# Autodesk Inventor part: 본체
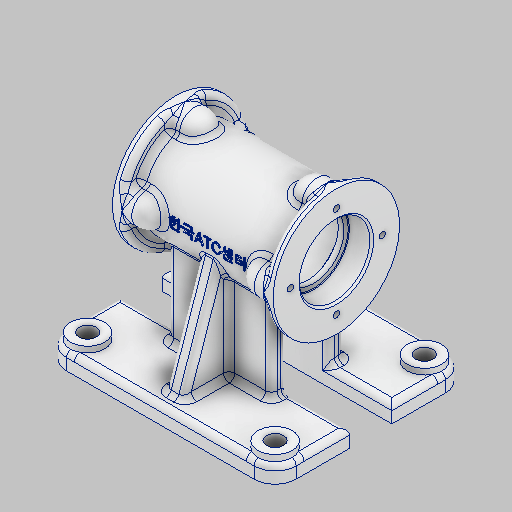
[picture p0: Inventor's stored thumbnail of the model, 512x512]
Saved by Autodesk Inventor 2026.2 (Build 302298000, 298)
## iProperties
Created: 2026-06
Part Number: 본체
Material: 알루미늄 6061
Document SubType Name: Modeling
Designer: sec7
Density: 2.7 g/cm^3
Appearance: 알루미늄 - 평지
Mass: 617.574 g
Surface Area: 687.665 cm^2
Volume: 228.731 cm^3
Author: sec7
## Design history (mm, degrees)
sketch "스케치1"
  geometry: L1 (-42, 0)-(42, 0); L2 (-42, 16)-(42, 16); L3 (42, 16)-(42, 0); L4 (-42, 18.5)-(-30.3, 18.5); L5 (-42, 18.5)-(-42, 0); L6 (-30, 18.2)-(-30, 0); L7 (-27, 0)-(-27, 17); L8 (-24, 20)-(24, 20); L9 (27, 17)-(27, 0); L10 (30, 0)-(30, 18.2); L11 (30.3, 18.5)-(42, 18.5); L12 (42, 18.5)-(42, 16); L13 (-42, 18.5)-(-42, 33); L14 (-42, 33)-(-37, 33); L15 (-37, 33)-(-37, 25); L16 (-37, 25)-(37, 25); L17 (37, 25)-(37, 33); L18 (37, 33)-(42, 33); L19 (42, 33)-(42, 18.5); L20 (-37, 29.455)-(-32, 29.455); L21 (-37, 25)-(-24.828, 25); A1 r 0.3 centre (-30.3, 18.2) between (-30, 18.2) and (-30.3, 18.5); A2 r 0.3 centre (30.3, 18.2) between (30.3, 18.5) and (30, 18.2); A3 r 3 centre (-24, 17) between (-24, 20) and (-27, 17); A4 r 3 centre (24, 17) between (27, 17) and (24, 20); A5 r 8 centre (-32, 21.455) between (-24.828, 25) and (-32, 29.455); 13 further points
  constraints: 42 end point, 14 point on line, 12 perpendicular, 10 point on circle, 9 tangent, 5 centre point, 4 vertical, 3 horizontal, 2 coincident, 2 equal radius, 2 midpoint, 1 collinear, 1 vertical alignment
  dimensions: "d1" = 84 distance of L1.start L1.end; "d3" = 32 diameter of L2 L1; "d4" = 37 diameter of L4 L1; "d5" = 40 diameter of L8 L1; "d6" = 54 distance between parallel lines of L9 L7; "d7" = 12 distance between parallel lines of L6 L5; "d8" = 37 diameter of L11 L1; "d9" = 12 distance between parallel lines of L3 L10; "d11" = 66 diameter of L14 L1; "d12" = 66 diameter of L18 L1; "d13" = 50 diameter of L16 L1; "d14" = 5 distance between parallel lines of L15 L13; "d15" = 5 distance between parallel lines of L19 L17; "d17" = 0.3 radius of A1; "d118" = 3 radius of A3; "d119" = 10 distance from line of L20.end L13; "d120" = 8 radius of A5; "d144" = 17.17158 distance from line of L21.end L13
revolve "회전1" sketch "스케치1" stored, may be unused: angle "d16" = 360 deg
node "작업 평면2"
sketch "스케치3"
  geometry: L1 (-60, 50)-(60, 50); L2 (60, 50)-(60, -50); L3 (60, -50)-(-60, -50); L4 (-60, -50)-(-60, 50); L5 (-60, 50)-(60, -50); L6 (60, 50)-(-60, -50); L7 (60, -11)-(-60, -11); L8 (60, 11)-(-60, 11); 1 further point
  constraints: 16 end point, 4 point on line, 3 perpendicular, 2 midpoint, 2 parallel, 1 horizontal
  dimensions: "d26" = 120 distance of L2.end L3.end; "d27" = 100 distance of L1.end L2.end; "d28" = 39 distance between parallel lines of L7 L3; "d29" = 39 distance between parallel lines of L1 L8
extrude "돌출2" join sketch "스케치3" distance "d30" = 9; taper "d31" = 0 deg
sketch "스케치4"
  geometry: L1 (49, -39)-(-49, -39); L2 (-49, -39)-(-49, 39); L3 (-49, 39)-(49, 39); L4 (49, 39)-(49, -39); L5 (49, -39)-(-49, 39); L6 (-49, -39)-(49, 39); C1 r 9 at (-49, 39); C2 r 9 at (49, 39); C3 r 9 at (49, -39); C4 r 9 at (-49, -39); 1 further point
  constraints: 12 end point, 4 centre point, 4 coincident, 2 midpoint, 2 parallel, 1 horizontal, 1 perpendicular
  dimensions: "d32" = 98 distance of L2.end L3.end; "d33" = 78 distance of L1.end L2.end; "d34" = 18 diameter of C1; "d35" = 18 diameter of C2; "d36" = 18 diameter of C3; "d37" = 18 diameter of C4
extrude "돌출3" join sketch "스케치4" distance "d38" = 3; taper "d39" = 0 deg
sketch "스케치5"
  geometry: L1 (0, 0)-(98, 0); L2 (98, 0)-(98, 78); L3 (98, 78)-(0, 78); L4 (0, 78)-(0, 0); C1 r 9 at (0, 0) reference; C2 r 9 at (98, 78) reference; C3 r 4.5 at (0, 0); C4 r 4.5 at (0, 78); C5 r 4.5 at (98, 78); C6 r 4.5 at (98, 0); 1 further point
  constraints: 8 end point, 4 centre point, 4 coincident, 2 parallel, 1 horizontal, 1 perpendicular
  dimensions: "d40" = 9 diameter of C3; "d41" = 9 diameter of C4; "d42" = 9 diameter of C5; "d43" = 9 diameter of C6
extrude "돌출4" cut sketch "스케치5" extent not by distance; stored distance "d44" = 0; taper "d45" = 0 deg
sketch "스케치6"
  geometry: L1 (-60, 11)-(60, 11) reference; L2 (60, -11)-(-60, -11) reference; L3 (-27, -11)-(27, -11); L4 (-27, 11)-(27, 11); L5 (-27, -11)-(-27, -19); L6 (-27, -19)-(27, -19); L7 (27, -19)-(27, -11); L8 (-27, 11)-(-27, 19); L9 (-27, 19)-(27, 19); L10 (27, 19)-(27, 11); 7 further points
  constraints: 16 end point, 4 midpoint, 4 perpendicular, 2 horizontal, 2 vertical
  dimensions: "d46" = 54 distance of L3.start L3.end; "d47" = 54 distance of L4.start L4.end; "d48" = 8 distance of L3.start L5.end; "d49" = 8 distance of L4.start L8.end
extrude "돌출5" join sketch "스케치6" stored distance "d50" = 10; taper "d51" = 0 deg
sketch "스케치7"
  geometry: L1 (-61, 50)-(-61, 11) reference; L2 (-17.454, 28.006)-(-61, 43); L3 (-70, 50)-(-61, 50) reference; L4 (-61, 19)-(-16.248, 19) reference; 2 further points
  constraints: 2 end point, 1 point on line, 2 other
  dimensions: "d52" = 7 distance from line of L2.end L3; "d53" = 19 deg angle of L4 L2
feature "리브1" sketch "스케치7" dims "d54" = 1, "d55" = 10, "d56" = 0, "d57" = 0, "d58" = 1, "d59" = 1
node "작업 평면1"
sketch "스케치2"
  geometry: L1 (25, 0)-(-25, 0); L2 (0, 25)-(0, -25); C1 r 8 at (25, 0); C2 r 8 at (0, 25); C3 r 8 at (-25, 0); C4 r 8 at (0, -25); A1 r 25 centre (0, 0) between (25, 0) and (0, 25) reference; 9 further points
  constraints: 4 centre point, 4 end point, 4 point on circle, 1 horizontal, 1 vertical
  dimensions: "d19" = 16 diameter of C1; "d20" = 16 diameter of C2; "d21" = 16 diameter of C3; "d22" = 16 diameter of C4; "d73" = 50 distance of L1.start L1.end; "d74" = 50 distance of L2.start L2.end
extrude "돌출1" join sketch "스케치2" distance "d23" = 5; taper "d24" = 0 deg
sketch "스케치10"
  geometry: L1 (-3.55, 23.157)-(3.55, 23.157); A1 r 25 centre (0, 0) between (23.72, 7.897) and (7.897, 23.72) reference; A2 r 25 centre (0, 0) between (-7.897, 23.72) and (-23.72, 7.897) reference; A3 r 8 centre (0, 25) between (7.897, 23.72) and (-7.897, 23.72) reference; A4 r 25 centre (0, 0) between (7.897, 23.72) and (-7.897, 23.72); A5 r 4 centre (0, 25) between (-3.55, 23.157) and (3.55, 23.157); 1 further point
  constraints: 4 point on circle, 2 centre point, 2 coincident, 2 end point, 1 horizontal
revolve "회전3" sketch "스케치10" stored, may be unused: angle "d71" = 180 deg
fillet "모깎기1" dims "d72" = 3
fillet "모깎기2" dims "d95" = 3
sketch "스케치13"
  geometry: L1 (-42, 0)-(42, 0); L2 (-42, 16)-(42, 16); L3 (42, 16)-(42, 0); L4 (-42, 18.5)-(-30.3, 18.5); L5 (-42, 18.5)-(-42, 0); L6 (-30, 18.2)-(-30, 0); L7 (-27, 0)-(-27, 17); L8 (-24, 20)-(24, 20); L9 (27, 17)-(27, 0); L10 (30, 0)-(30, 18.2); L11 (30.3, 18.5)-(42, 18.5); L12 (42, 18.5)-(42, 16); L13 (-42, 18.5)-(-42, 33); L14 (-42, 33)-(-37, 33); L15 (-37, 33)-(-37, 25); L16 (-37, 25)-(37, 25); L17 (37, 25)-(37, 33); L18 (37, 33)-(42, 33); L19 (42, 33)-(42, 18.5); A1 r 0.3 centre (-30.3, 18.2) between (-30, 18.2) and (-30.3, 18.5); A2 r 0.3 centre (30.3, 18.2) between (30.3, 18.5) and (30, 18.2); A3 r 3 centre (-24, 17) between (-24, 20) and (-27, 17); A4 r 3 centre (24, 17) between (27, 17) and (24, 20); 21 further points
  constraints: 38 end point, 12 perpendicular, 8 point on circle, 8 point on line, 8 tangent, 4 centre point, 4 coincident, 4 vertical, 2 equal radius, 2 horizontal, 2 midpoint, 1 vertical alignment
  dimensions: "d156" = 84 distance of L1.start L1.end; "d157" = 32 diameter of L2 L1; "d158" = 37 diameter of L4 L1; "d159" = 40 diameter of L8 L1; "d160" = 54 distance between parallel lines of L9 L7; "d161" = 12 distance between parallel lines of L6 L5; "d162" = 37 diameter of L11 L1; "d163" = 12 distance between parallel lines of L3 L10; "d164" = 84 distance from line of L2.start L12; "d165" = 66 diameter of L14 L1; "d166" = 66 diameter of L18 L1; "d167" = 50 diameter of L16 L1; "d168" = 5 distance between parallel lines of L15 L13; "d169" = 5 distance between parallel lines of L19 L17; "d170" = 0.3 radius of A1; "d173" = 3 radius of A3
revolve "회전4" sketch "스케치13" stored, may be unused: angle "d174" = 360 deg
sketch "스케치14"
  geometry: L1 (-70, 50)-(-70, 11) reference; L2 (-70, -11)-(-70, -50) reference; L3 (-70, 11)-(-70, -11); L4 (-70, 0)-(-50, 0); L5 (-61, 11)-(-22.45, 11) reference; L6 (-50, 11)-(-50, -11); L7 (-61, -11)-(-22.45, -11) reference; L8 (-61, 11)-(-22.45, 11) reference; C1 r 33 at (0, 0) reference; 1 further point
  constraints: 6 end point, 2 vertical, 1 horizontal, 1 midpoint, 1 point on line
  dimensions: "d175" = 20 distance of L4.start L4.end
feature "리브2" sketch "스케치14" dims "d176" = 1, "d177" = 10, "d178" = 0, "d179" = 0, "d180" = 1, "d181" = 1
node "작업 평면3"
sketch "스케치15"
  geometry: L1 (-60, -70)-(60, -70) reference; L2 (0, -70)-(0, 0); 1 further point
  constraints: 2 end point, 1 coincident, 1 midpoint, 1 vertical, 1 other
  dimensions: "d183" = 70 distance of L2.start L2.end (derived)
feature "엠보싱1" sketch "스케치15" dims "d1" = 84, "d3" = 32, "d4" = 37, "d5" = 40, "d6" = 54, "d7" = 12, "d8" = 37, "d9" = 12, "d11" = 66, "d12" = 66, "d13" = 50, "d14" = 5, "d15" = 5, "d17" = 0.3, "d118" = 3, "d119" = 10, "d120" = 8, "d144" = 17.17158, "d184" = 0.5, "d185" = 0
sketch "스케치16"
  geometry: L1 (0, 24)-(0, -24); L2 (-24, 0)-(24, 0); A1 r 24 centre (0, 0) between (0, 24) and (0, -24); 5 further points
  constraints: 5 point on circle, 4 coincident, 4 end point, 1 centre point, 1 perpendicular, 1 vertical
  dimensions: "d186" = 48 diameter of A1; "d187" = 48 distance of L2.start L2.end; "d188" = 48 distance of L1.start L1.end; "d189" = 24 distance from line of point (0, 24) L2
hole "구멍2" sketch "스케치16" at (0, 24), (-24, 0), (24, 0), (0, -24) diameter "d190" = 3.242; stored, may be unused: countersink angle "d194" = 90 deg, drill point angle "d196" = 120 deg; dims "d191" = 8, "d192" = 4, "d193" = 2, "d195" = 10
chamfer "모따기1" distance "d197" = 1; stored, may be unused: second distance "d198" = 2, angle "d199" = 45 deg
chamfer "모따기2" distance "d200" = 1; stored, may be unused: second distance "d201" = 2, angle "d202" = 45 deg
fillet "모깎기4" dims "d204" = 3
fillet "모깎기5" dims "d205" = 11
fillet "모깎기6" dims "d206" = 3
fillet "모깎기7" dims "d207" = 3
fillet "모깎기8" dims "d208" = 3
fillet "모깎기9" dims "d209" = 2
fillet "모깎기10" dims "d210" = 3
fillet "모깎기11" dims "d211" = 3
fillet "모깎기12" dims "d212" = 3
fillet "모깎기13" dims "d213" = 3
feature "ى耀ً耀ٍ耀ُ耀ّ耀ٓ耀ٕ耀ٗ耀" dims "d1" = 84, "d3" = 32, "d4" = 37, "d5" = 40, "d6" = 54, "d7" = 12, "d8" = 37, "d9" = 12, "d11" = 66, "d12" = 66, "d13" = 50, "d14" = 5, "d15" = 5, "d16" = 360 deg, "d17" = 0.3, "d18" = -37, "d19" = 16, "d20" = 16, "d21" = 16, "d22" = 16, "d23" = 5, "d24" = 0, "d25" = -70, "d26" = 120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
feature "࠲耀࠴耀࠶耀࠸耀࠺耀࠼耀࠾耀ࡀ耀" dims "d1" = 84, "d3" = 32, "d4" = 37, "d5" = 40, "d6" = 54, "d7" = 12, "d8" = 37, "d9" = 12, "d11" = 66, "d12" = 66, "d13" = 50, "d14" = 5, "d15" = 5, "d16" = 360 deg, "d17" = 0.3, "d18" = -37, "d19" = 16, "d20" = 16, "d21" = 16, "d22" = 16, "d23" = 5, "d24" = 0, "d25" = -70, "d26" = 120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
node "솔리드1"
mirror "미러1"
pattern_circular "원형 패턴1" dims angle "d93" = 360 deg
mirror "미러3"
mirror "미러4"
feature "A9D066F2-1C7D-4E18-AEED-F7BC21143FA4" dims "d190" = 3.242, "d191" = 8, "d192" = 4, "d193" = 2, "d194" = 90 deg, "d195" = 10, "d196" = 120 deg
